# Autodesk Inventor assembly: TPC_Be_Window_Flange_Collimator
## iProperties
Shininess: 64.0
Length Units: 11269
Angle Units: 11279
Time Units: 11290
Mass Units: 11283
Length Display Precision: 3
Angle Display Precision: 2
Compacted: True
Created: 2004-07
Part Number: TPC_Be_Window_Flange_Collimator
Document SubType Name: Assembly
Designer: John Blackburn
Manufacturer: Standard
Standards Organization: Custom
Density: 0.0
Volumn: 0.0
Area: 0.0
PropertySet Name: Model Information
Control State: 0
Master: False
Checked Out: False
Author: John Blackburn
